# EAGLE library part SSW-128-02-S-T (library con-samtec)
THROUGH-HOLE .025" SQ POST SOCKET Source: Samtec SSW.pdf
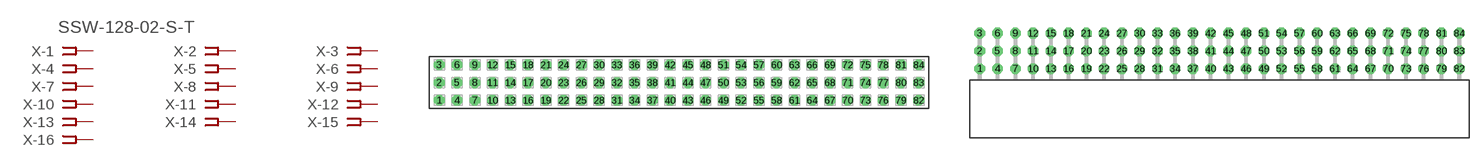
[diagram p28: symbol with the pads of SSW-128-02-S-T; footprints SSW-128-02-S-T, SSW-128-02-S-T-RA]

Designator prefix X; gates -1=FPINV -2=FPIN -3=FPIN -4=FPIN -5=FPIN -6=FPIN -7=FPIN -8=FPIN -9=FPIN -10=FPIN -11=FPIN -12=FPIN -13=FPIN -14=FPIN -15=FPIN -16=FPIN -17=FPIN -18=FPIN -19=FPIN -20=FPIN -21=FPIN -22=FPIN -23=FPIN -24=FPIN -25=FPIN -26=FPIN -27=FPIN -28=FPIN -29=FPIN -30=FPIN -31=FPIN -32=FPIN -33=FPIN -34=FPIN -35=FPIN -36=FPIN -37=FPIN -38=FPIN -39=FPIN -40=FPIN -41=FPIN -42=FPIN -43=FPIN -44=FPIN -45=FPIN -46=FPIN -47=FPIN -48=FPIN -49=FPIN -50=FPIN -51=FPIN -52=FPIN -53=FPIN -54=FPIN -55=FPIN -56=FPIN -57=FPIN -58=FPIN -59=FPIN -60=FPIN -61=FPIN -62=FPIN -63=FPIN -64=FPIN -65=FPIN -66=FPIN -67=FPIN -68=FPIN -69=FPIN -70=FPIN -71=FPIN -72=FPIN -73=FPIN -74=FPIN -75=FPIN -76=FPIN -77=FPIN -78=FPIN -79=FPIN -80=FPIN -81=FPIN -82=FPIN -83=FPIN -84=FPIN

## SSW-128-02-S-T (MPN: SSW-128-02-S-T; OC_FARNELL: unknown; OC_NEWARK: 82P9847)  [SSW-128-02-S-T]
1  -1:1  pas
2  -2:1  pas
3  -3:1  pas
4  -4:1  pas
5  -5:1  pas
6  -6:1  pas
7  -7:1  pas
8  -8:1  pas
9  -9:1  pas
10  -10:1  pas
11  -11:1  pas
12  -12:1  pas
13  -13:1  pas
14  -14:1  pas
15  -15:1  pas
16  -16:1  pas
17  -17:1  pas
18  -18:1  pas
19  -19:1  pas
20  -20:1  pas
21  -21:1  pas
22  -22:1  pas
23  -23:1  pas
24  -24:1  pas
25  -25:1  pas
26  -26:1  pas
27  -27:1  pas
28  -28:1  pas
29  -29:1  pas
30  -30:1  pas
31  -31:1  pas
32  -32:1  pas
33  -33:1  pas
34  -34:1  pas
35  -35:1  pas
36  -36:1  pas
37  -37:1  pas
38  -38:1  pas
39  -39:1  pas
40  -40:1  pas
41  -41:1  pas
42  -42:1  pas
43  -43:1  pas
44  -44:1  pas
45  -45:1  pas
46  -46:1  pas
47  -47:1  pas
48  -48:1  pas
49  -49:1  pas
50  -50:1  pas
51  -51:1  pas
52  -52:1  pas
53  -53:1  pas
54  -54:1  pas
55  -55:1  pas
56  -56:1  pas
57  -57:1  pas
58  -58:1  pas
59  -59:1  pas
60  -60:1  pas
61  -61:1  pas
62  -62:1  pas
63  -63:1  pas
64  -64:1  pas
65  -65:1  pas
66  -66:1  pas
67  -67:1  pas
68  -68:1  pas
69  -69:1  pas
70  -70:1  pas
71  -71:1  pas
72  -72:1  pas
73  -73:1  pas
74  -74:1  pas
75  -75:1  pas
76  -76:1  pas
77  -77:1  pas
78  -78:1  pas
79  -79:1  pas
80  -80:1  pas
81  -81:1  pas
82  -82:1  pas
83  -83:1  pas
84  -84:1  pas

## SSW-128-02-S-TRA (MPN: SSW-128-02-S-T-RA; OC_FARNELL: unknown; OC_NEWARK: 82P9848)  [SSW-128-02-S-T-RA]
Pads as for SSW-128-02-S-T

## Footprint SSW-128-02-S-T (pad centres in mm)
THROUGH-HOLE .025" SQ POST SOCKET Source: Samtec SSW.pdf
drill 1 pad 1.5 octagon: 1 -34.29,-2.54; 2 -34.29,0; 3 -34.29,2.54; 4 -31.75,-2.54; 5 -31.75,0; 6 -31.75,2.54; 7 -29.21,-2.54; 8 -29.21,0; 9 -29.21,2.54; 10 -26.67,-2.54; 11 -26.67,0; 12 -26.67,2.54; 13 -24.13,-2.54; 14 -24.13,0; 15 -24.13,2.54; 16 -21.59,-2.54; 17 -21.59,0; 18 -21.59,2.54; 19 -19.05,-2.54; 20 -19.05,0; 21 -19.05,2.54; 22 -16.51,-2.54; 23 -16.51,0; 24 -16.51,2.54; 25 -13.97,-2.54; 26 -13.97,0; 27 -13.97,2.54; 28 -11.43,-2.54; 29 -11.43,0; 30 -11.43,2.54; 31 -8.89,-2.54; 32 -8.89,0; 33 -8.89,2.54; 34 -6.35,-2.54; 35 -6.35,0; 36 -6.35,2.54; 37 -3.81,-2.54; 38 -3.81,0; 39 -3.81,2.54; 40 -1.27,-2.54; 41 -1.27,0; 42 -1.27,2.54; 43 1.27,-2.54; 44 1.27,0; 45 1.27,2.54; 46 3.81,-2.54; 47 3.81,0; 48 3.81,2.54; 49 6.35,-2.54; 50 6.35,0; 51 6.35,2.54; 52 8.89,-2.54; 53 8.89,0; 54 8.89,2.54; 55 11.43,-2.54; 56 11.43,0; 57 11.43,2.54; 58 13.97,-2.54; 59 13.97,0; 60 13.97,2.54; 61 16.51,-2.54; 62 16.51,0; 63 16.51,2.54; 64 19.05,-2.54; 65 19.05,0; 66 19.05,2.54; 67 21.59,-2.54; 68 21.59,0; 69 21.59,2.54; 70 24.13,-2.54; 71 24.13,0; 72 24.13,2.54; 73 26.67,-2.54; 74 26.67,0; 75 26.67,2.54; 76 29.21,-2.54; 77 29.21,0; 78 29.21,2.54; 79 31.75,-2.54; 80 31.75,0; 81 31.75,2.54; 82 34.29,-2.54; 83 34.29,0; 84 34.29,2.54

## Footprint SSW-128-02-S-T-RA (pad centres in mm)
THROUGH-HOLE .025" SQ POST SOCKET Source: Samtec SSW.pdf
drill 1 pad 1.5 octagon: 1 -34.29,1.524; 2 -34.29,4.064; 3 -34.29,6.604; 4 -31.75,1.524; 5 -31.75,4.064; 6 -31.75,6.604; 7 -29.21,1.524; 8 -29.21,4.064; 9 -29.21,6.604; 10 -26.67,1.524; 11 -26.67,4.064; 12 -26.67,6.604; 13 -24.13,1.524; 14 -24.13,4.064; 15 -24.13,6.604; 16 -21.59,1.524; 17 -21.59,4.064; 18 -21.59,6.604; 19 -19.05,1.524; 20 -19.05,4.064; 21 -19.05,6.604; 22 -16.51,1.524; 23 -16.51,4.064; 24 -16.51,6.604; 25 -13.97,1.524; 26 -13.97,4.064; 27 -13.97,6.604; 28 -11.43,1.524; 29 -11.43,4.064; 30 -11.43,6.604; 31 -8.89,1.524; 32 -8.89,4.064; 33 -8.89,6.604; 34 -6.35,1.524; 35 -6.35,4.064; 36 -6.35,6.604; 37 -3.81,1.524; 38 -3.81,4.064; 39 -3.81,6.604; 40 -1.27,1.524; 41 -1.27,4.064; 42 -1.27,6.604; 43 1.27,1.524; 44 1.27,4.064; 45 1.27,6.604; 46 3.81,1.524; 47 3.81,4.064; 48 3.81,6.604; 49 6.35,1.524; 50 6.35,4.064; 51 6.35,6.604; 52 8.89,1.524; 53 8.89,4.064; 54 8.89,6.604; 55 11.43,1.524; 56 11.43,4.064; 57 11.43,6.604; 58 13.97,1.524; 59 13.97,4.064; 60 13.97,6.604; 61 16.51,1.524; 62 16.51,4.064; 63 16.51,6.604; 64 19.05,1.524; 65 19.05,4.064; 66 19.05,6.604; 67 21.59,1.524; 68 21.59,4.064; 69 21.59,6.604; 70 24.13,1.524; 71 24.13,4.064; 72 24.13,6.604; 73 26.67,1.524; 74 26.67,4.064; 75 26.67,6.604; 76 29.21,1.524; 77 29.21,4.064; 78 29.21,6.604; 79 31.75,1.524; 80 31.75,4.064; 81 31.75,6.604; 82 34.29,1.524; 83 34.29,4.064; 84 34.29,6.604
